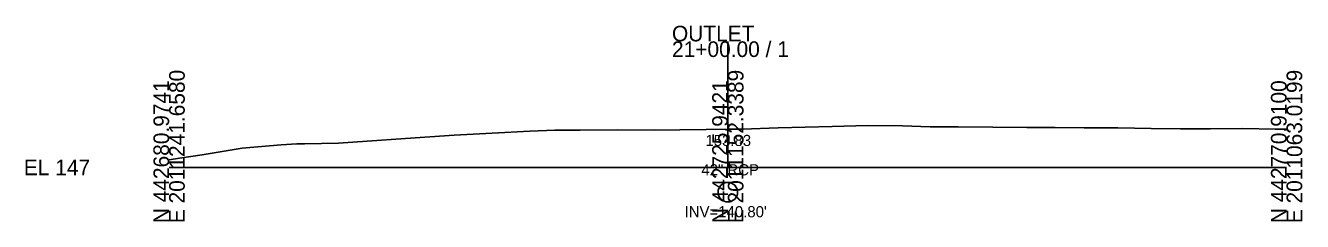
# Model space of a CAD drawing. Extents: x -26 to 1203, y -15 to 9526.
# Drawn here: x 974.3 to 1202.8, y 990.3 to 1025.4 of the extents above; entities that cross this region are included whole.
import ezdxf

# ---------------------------------------------------------------- set-up
doc = ezdxf.new("R2010")
doc.units = 0
for name, color, linetype in [('Exist Cross Section Cell', 7, 'Continuous'), ('Exist XS Center Line Elevation Label', 7, 'Continuous'), ('Exist XS Ground Line', 7, 'Continuous'), ('Prop XSC Text', 7, 'Continuous')]:
    doc.layers.add(name, color=color, linetype=linetype)

msp = doc.modelspace()

# ---------------------------------------------------------------- linework, layer by layer
at = {"layer": 'Exist Cross Section Cell'}
for p, q in [((1100, 1000), (1100, 1022.58)), ((1000, 1000), (1100, 1000)), ((1100, 1000), (1200, 1000))]:
    msp.add_line(p, q, dxfattribs=at)
at = {"layer": 'Exist XS Ground Line'}
msp.add_lwpolyline([(1000, 1001.36), (1001.86, 1001.65), (1005.93, 1002.25), (1013.05, 1003.42), (1020.07, 1004.05), (1022.85, 1004.23), (1024.25, 1004.22), (1030.3, 1004.32), (1035.44, 1004.71), (1042.31, 1005.18), (1046.64, 1005.48), (1051.03, 1005.78), (1057.84, 1006.12), (1064.55, 1006.49), (1069.03, 1006.7), (1073.58, 1006.68), (1080.23, 1006.74), (1086.79, 1006.7), (1091.42, 1006.72), (1096.12, 1006.78), (1100, 1006.83), (1102.62, 1006.87), (1109.02, 1007.06), (1113.81, 1007.22), (1118.67, 1007.34), (1125.01, 1007.53), (1131.26, 1007.43), (1136.21, 1007.29), (1141.22, 1007.28), (1147.4, 1007.19), (1153.5, 1007.16), (1158.6, 1007.14), (1163.77, 1007.07), (1169.79, 1007.06), (1175.74, 1006.94), (1180.99, 1006.92), (1186.31, 1006.93), (1192.19, 1006.98), (1197.98, 1006.86), (1200, 1006.82)], dxfattribs=at)
at = {"layer": 'Prop XSC Text'}
msp.add_circle((1100, 995.55), 1.75, dxfattribs=at)

# ---------------------------------------------------------------- texts
at = {"layer": 'Exist Cross Section Cell'}
for s, p in [('OUTLET', (1090, 1022.58)), ('21+00.00 / 1', (1090, 1019.78)), ('EL 147', (974, 998.6))]:
    msp.add_text(s, height=2.8, dxfattribs=at).set_placement(p)
for s, p in [('E 2011241.6580', (1002.8, 990)), ('E 2011152.3389', (1102.8, 990)), ('E 2011063.0199', (1202.8, 990)), ('N 442680.9741', (1000, 990)), ('N 442725.9421', (1100, 990)), ('N 442770.9100', (1200, 990))]:
    msp.add_text(s, height=2.8, rotation=90, dxfattribs=at).set_placement(p)
at = {"layer": 'Exist XS Center Line Elevation Label'}
msp.add_text('153.83', height=2, dxfattribs=at).set_placement((1095.99, 1003.83))
at = {"layer": 'Prop XSC Text'}
for s, p in [('42" RCP', (1095.26, 998.57)), ("INV=140.80'", (1092.26, 991.06))]:
    msp.add_text(s, height=2, dxfattribs=at).set_placement(p)

doc.saveas('drawing.dxf')
